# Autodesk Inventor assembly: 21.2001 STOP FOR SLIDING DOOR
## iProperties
Created: 2007-05
Part Number: 21.2001 STOP FOR SLIDING DOOR
Document SubType Name: Assembly
Designer: Andy Moles
Author: Andy Moles
